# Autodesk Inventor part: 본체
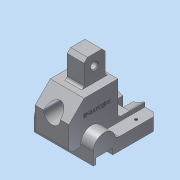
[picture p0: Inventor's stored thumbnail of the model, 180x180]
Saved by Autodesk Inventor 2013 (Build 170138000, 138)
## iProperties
Created: 2016-11
Part Number: 본체
Material: 알루미늄 6061
Document SubType Name: Modeling
Designer: dgall
Density: 2.71 g/cm^3
Mass: 463.602 g
Surface Area: 317.215 cm^2
Volume: 171.071 cm^3
Author: dgall
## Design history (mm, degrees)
sketch "스케치1"
  geometry: L1 (-13, 0)-(-13, -15); L2 (-13, -15)-(-10, -15); L3 (-10, -15)-(-10, -8); L4 (-10, -8)-(10, -8); L5 (10, -8)-(10, -15); L6 (10, -15)-(63, -15); L7 (63, -15)-(63, 0); L8 (63, 0)-(13, 0); A1 r 13 centre (0, 0) between (13, 0) and (-13, 0); 1 further point
  constraints: 16 end point, 5 parallel, 2 horizontal alignment, 2 point on circle, 1 centre point, 1 coincident, 1 collinear, 1 perpendicular, 1 tangent, 1 vertical
  dimensions: "d0" = 26 diameter of A1; "d1" = 3 distance of L1.end L2.end; "d2" = 20 distance of L3.end L4.end; "d3" = 63 horizontal distance of L6.end point (0, 0); "d4" = 7 distance of L2.end L3.end; "d5" = 15 distance of L6.end L7.end
extrude "돌출1" new body sketch "스케치1" distance "d6" = 15; taper "d7" = 0 deg
node "작업 평면1"
sketch "스케치2"
  geometry: L1 (0, 13)-(0, 63) reference; L2 (0, 63)-(-15, 63) reference; L3 (-15, 63)-(-15, 10) reference; L4 (-15, 10)-(-8, 10) reference; L5 (-8, 10)-(-8, -10) reference; L6 (-8, -10)-(-15, -10) reference; L7 (-15, -10)-(-15, -13) reference; L8 (-15, -13)-(0, -13) reference; A1 r 13 centre (0, 0) between (0, -13) and (0, 13) reference; 1 further point
extrude "돌출2" join sketch "스케치2" distance "d9" = 15; taper "d10" = 0 deg
sketch "스케치3"
  geometry: L1 (15, -13)-(0, -13) reference; L2 (15, -10)-(15, -13) reference; L3 (8, -10)-(15, -10) reference; L4 (8, 10)-(8, -10) reference; L5 (15, 10)-(8, 10) reference; L6 (15, 63)-(15, 10) reference; L7 (-5, 63)-(-5, 31); L8 (-5, 31)-(-45, 31); L9 (-45, 31)-(-45, -9); L10 (-45, -9)-(-27, -27); L11 (-27, -27)-(3, -27); L12 (-5, 63)-(15, 63); L13 (15, 63)-(15, 11); L14 (3, -27)-(3, -13); L15 (3, -13)-(15, -13); 1 further point
  constraints: 18 end point, 4 perpendicular, 2 point on line, 1 collinear, 1 horizontal alignment, 1 vertical
  dimensions: "d11" = 45 deg angle of L9 L10; "d12" = 18 horizontal distance of L9.end L10.end; "d14" = 30 distance of L10.end L11.end; "d15" = 20 distance between parallel lines of L6 L7; "d16" = 90 distance from line of point (0, 63) L11; "d17" = 58 distance between parallel lines of L11 L8; "d18" = 60 distance between parallel lines of L6 L9
extrude "돌출3" join sketch "스케치3" distance "d21" = 40; taper "d22" = 0 deg
sketch "스케치5"
  geometry: L1 (0, 0)-(40, 0) reference; L2 (55, 60)-(-15, 60) reference; 3 further points
  constraints: 1 midpoint, 1 vertical alignment
  dimensions: "d23" = 42 distance from line of L2 point (20, 18)
hole "구멍1" sketch "스케치5" at (20, 18) diameter "d24" = 20; stored, may be unused: countersink angle "d28" = 90 deg, drill point angle "d30" = 118 deg; dims "d25" = 6, "d26" = 28, "d27" = 7, "d29" = 8
sketch "스케치6"
  geometry: L1 (0, 15)-(-70, 15) reference; L2 (-55, -5)-(-15, -5) reference; L3 (-29, 1.373)-(-29, 15); L4 (-41, 1.373)-(-41, 15); C1 r 10 at (-35, -27) reference; A1 r 29 centre (-35, -27) between (-16.106, -5) and (-29, 1.373); A2 r 29 centre (-35, -27) between (-41, 1.373) and (-53.894, -5)
  constraints: 4 end point, 4 point on circle, 4 point on line, 2 centre point, 1 coincident, 1 concentric, 1 parallel, 1 perpendicular
  dimensions: "d32" = 6 distance from line of C1.centre L4; "d33" = 6 distance from line of L3 C1.centre; "d34" = 29 radius of A1
extrude "돌출4" cut sketch "스케치6" distance "d35" = 18; taper "d36" = 0 deg
node "작업 평면2"
sketch "스케치7"
  geometry: L1 (-75, 1)-(-45, 1); L2 (-45, 1)-(-45, 26); L3 (-45, 26)-(-75, 26); L4 (-75, 26)-(-75, 1); L5 (-5, 31)-(-45, 31) reference; L6 (15, 45)-(15, 63) reference; 1 further point
  constraints: 8 end point, 2 parallel, 1 horizontal, 1 perpendicular, 1 vertical alignment
  dimensions: "d38" = 25 distance of L3.end L1.start; "d40" = 5 distance between parallel lines of L5 L3; "d41" = 90 distance between parallel lines of L6 L4
extrude "돌출5" join sketch "스케치7" distance "d42" = 20; taper "d43" = 0 deg
sketch "스케치8"
  geometry: L1 (-75, 26)-(-75, 1) reference; L2 (15, 10)-(15, 63) reference; C1 r 4 at (-62, 13.5); 2 further points
  constraints: 1 centre point, 1 horizontal alignment, 1 midpoint
  dimensions: "d44" = 8 diameter of C1; "d45" = 77 distance from line of L2 C1.centre
extrude "돌출6" cut sketch "스케치8" distance "d46" = 20; taper "d47" = 0 deg
sketch "스케치9"
  geometry: L1 (-15, 50)-(0, 50) reference; L2 (-55, 50)-(-70, 50) reference; L3 (-25, -40)-(-45, -40) reference; L4 (-16.106, 32)-(-53.894, 32) reference; L5 (-16.106, 50)-(-16.106, 32) reference; L6 (-16.106, 32)-(-53.894, 32) reference; L7 (-53.894, 32)-(-53.894, 50) reference; L8 (-55, 50)-(-53.894, 50) reference; L9 (-55, 50)-(-55, 18) reference; L10 (-55, 18)-(-15, 18) reference; L11 (-15, 50)-(-15, 18) reference; L12 (-16.106, 50)-(-15, 50) reference; L13 (0, -3)-(-70, -3) reference; L14 (-62.5, 32)-(-7.5, 32); 3 further points
  constraints: 2 end point, 2 midpoint, 1 vertical alignment
  dimensions: "d48" = 18 distance from line of L1 L14.end; "d49" = 18 distance from line of L2 L14.start; "d50" = 55 distance of L14.end L14.start
hole "구멍2" sketch "스케치9" at (-7.5, 32), (-62.5, 32) diameter "d51" = 3.242; stored, may be unused: countersink angle "d55" = 90 deg, drill point angle "d57" = 118 deg; dims "d52" = 6, "d53" = 28, "d54" = 7, "d56" = 8
fillet "모깎기1" dims "d58" = 3
chamfer "모따기1" distance "d59" = 1; stored, may be unused: second distance "d60" = 2, angle "d61" = 45 deg
chamfer "모따기2" distance "d62" = 4; stored, may be unused: second distance "d63" = 2, angle "d64" = 45 deg
chamfer "모따기3" distance "d65" = 5; stored, may be unused: second distance "d66" = 2, angle "d67" = 45 deg
sketch "스케치10"
  geometry: L1 (-8, 31)-(-45, 31) reference; 2 further points
  constraints: 1 other
  dimensions: "d68" = 25 distance from line of L1 point (-27, 6); "d69" = 18 horizontal distance of point (-45, -9) point (-27, 6)
extrude "돌출7" join sketch "스케치10" distance "d70" = 0.5; taper "d71" = 0 deg
fillet "모깎기2" dims "d72" = 5
node "솔리드1"
node "투영된 루프1"
node "투영된 루프2"
other parameters: "d31" = 58
